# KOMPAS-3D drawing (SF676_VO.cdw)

Views: Спереди 1, Проекционный вид 4
Referenced files in G:\task_260097 станки 6Р12\на отправку\: 6Р12 Общий вид станка.cdw
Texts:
  Станок фрезерный СФ676
  125 1 126 1 127 1 128 0 50 1|SPDS|125 1 126 1 127 1 128 0 50 1
  129 1 130 1 131 1 132 0 50 1|SPDS|129 1 130 1 131 1 132 0 50 1
  Normal
  Освещение LED 24V
  1. Мощность электродвигателя главного движения  3 кВт.
  4. Частоты вращения шпинделя:
  6. Минимальная подача стола:
  Станок фрезерный
  СФ676
Dimensions and other numbers on the sheet: 111; 1; 2; 3; 4; 5; 6; 7; 8; 9; 1:5; 1050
